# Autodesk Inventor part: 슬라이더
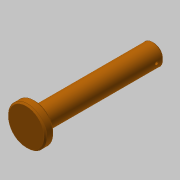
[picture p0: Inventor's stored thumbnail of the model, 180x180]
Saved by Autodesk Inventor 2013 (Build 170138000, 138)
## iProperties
Created: 2019-01
Part Number: 슬라이더
Material: 강철, 연강
Document SubType Name: Modeling
Designer: mduedu
Density: 7.86 g/cm^3
Mass: 120.7 g
Surface Area: 50.2627 cm^2
Volume: 15.3562 cm^3
Author: mduedu
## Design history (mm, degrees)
sketch "스케치1"
  geometry: L1 (0, 0)-(6, 0); L2 (6, 0)-(6, 13); L3 (6, 13)-(0, 13); L4 (0, 13)-(0, 0); L5 (6, 0)-(86, 0); L6 (86, 0)-(86, 7); L7 (86, 7)-(6, 7); L8 (6, 7)-(6, 0)
  constraints: 16 end point, 4 parallel, 2 horizontal, 2 perpendicular
  dimensions: "d0" = 86 distance between parallel lines of L6 L4; "d2" = 6 distance of L2.end L3.end; "d3" = 26 diameter of L3 L1; "d4" = 14 diameter of L7 L5
revolve "회전1" sketch "스케치1" stored, may be unused: angle "d5" = 90 deg
chamfer "모따기1" distance "d6" = 1; stored, may be unused: second distance "d7" = 2, angle "d8" = 45 deg
chamfer "모따기4" distance "d24" = 1; stored, may be unused: second distance "d25" = 2, angle "d28" = 30 deg
sketch "스케치3"
  geometry: L1 (86, 6)-(86, -6) reference; C1 r 1 at (81, 0); 1 further point
  constraints: 1 centre point, 1 horizontal alignment
  dimensions: "d34" = 2 diameter of C1; "d36" = 5 distance from line of C1.centre L1
extrude "돌출1" cut sketch "스케치3" stored distance "d37" = 10; taper "d38" = 0 deg
node "솔리드1"
